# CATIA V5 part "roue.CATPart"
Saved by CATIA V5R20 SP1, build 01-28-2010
Part number: roue
Bounding box of the stored display mesh (mm): x 330 to 530, y -437.416 to 437.416, z -1157.429 to -282.571
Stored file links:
  C:\Users\Nicolas\Documents\Ifma\2A\S3\iao\projet\nmine_IAO\roue.CATPart
  C:\Users\Nicolas\Documents\Ifma\2A\S3\iao\projet\Product1.CATProduct
  C:\Users\Nicolas\Documents\Ifma\2A\S3\iao\projet\nmine_IAO\bielle2.CATPart
  C:\Users\Nicolas\Documents\Ifma\2A\S3\iao\projet\nmine_IAO\triangle.CATPart
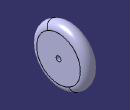
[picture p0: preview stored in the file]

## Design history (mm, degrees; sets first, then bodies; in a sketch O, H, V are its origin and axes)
Set1
  Line1: linked copy from another document
  Plane1: linked copy from another document
  DatumSurface1: linked copy from another document
  DatumSurface2: linked copy from another document
Body1 (main body)
  Sketch1 on zx-plane, origin (0, 0, 0), H (-1, 0, 0), V (0, 0, 1)
    arc A1 centre (-430, -382.5) radius 100 from (-330, -382.5) to (-530, -382.5) ccw
    line L1 (-330, -382.5) -> (-330, -682.5)
    line L2 (-330, -682.5) -> (-530, -682.5)
    line L3 (-530, -682.5) -> (-530, -382.5)
    reference projected line E1 (20, -720) -> (-150, -720) from Line1
    reference intersected line E2 through (-270, 0) direction (0, -1) from face of DatumSurface2
    length L2 = 200
    length L3 = 300
    distance E1 L2 = 37.5
    distance L1 E2 = 60
    horizontal: L2 H
    vertical: L1 V, L3 V
    tangency: L3 A1, L1 A1
  Shaft1: profile Sketch1, axis Line1, angle 360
